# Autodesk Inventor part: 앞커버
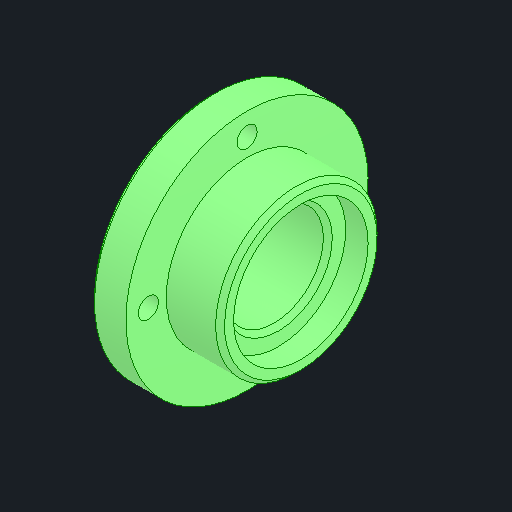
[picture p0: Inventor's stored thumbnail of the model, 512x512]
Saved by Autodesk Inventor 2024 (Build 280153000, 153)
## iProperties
Created: 2025-02
Part Number: 앞커버
Material: 강철, 연강
Document SubType Name: Modeling
Designer: kh_501
Density: 7.85 g/cm^3
Appearance: 기본값
Author: jhkim
Sending System: Autodesk Inventor 2025
Preprocessor: ST-DEVELOPER v20
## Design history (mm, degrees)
feature "솔리드1"
node "솔리드2"
